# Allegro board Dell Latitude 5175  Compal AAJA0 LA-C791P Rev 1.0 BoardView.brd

Outline 223.08 x 166.9 mm; copper layers: TOP, VCC, GND1, IN1, IN2, GND2, IN3, GND3, IN4, BOTTOM. Coordinates in mm from the lower left corner of the outline.

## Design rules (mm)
constraint set DEFAULT: min track width 0.119
net group 80H-DPAUX_5.6/3.1/3.1/5.6: nets PD_AUX_N PD_AUX_P
net group DDRA-CTRL: nets M_A_CS0_N M_A_CS1_N
net group DDRB-CTRL: nets M_B_CS0_N M_B_CS1_N
net group DIFFPAIR20: nets USB20_N9_CONN USB20_P9_CONN
net group I2C0_SCL: nets I2C0_SCL I2C0_SDA
net group PCIE-WWAN: nets PCIE_PRX_DTX_N6 PCIE_PRX_DTX_P6
net group S-12/12: nets PCIE_RCOMPN PCIE_RCOMPP
net group CLK: nets CK_XDP CK_XDP# CLK_PCIE2 CLK_PCIE2# CLK_PCIE3 CLK_PCIE3# CLK_PCIE3#_R CLK_PCIE3_R CLK_PCIE4 CLK_PCIE4# CLK_PCIE4#_R CLK_PCIE4_R SKYCAM_CSI_CLK_D SKYCAM_CSI_CLK_D# SKYCAM_CSI_CLK_D#_L SKYCAM_CSI_CLK_D_L SKYCAM_USER_CSI_CLK_D SKYCAM_USER_CSI_CLK_D# SKYCAM_USER_CSI_CLK_D#_L SKYCAM_USER_CSI_CLK_D_L
net group CSI: nets SKYCAM_CSI0_D SKYCAM_CSI0_D# SKYCAM_CSI0_D#_L SKYCAM_CSI0_D_L SKYCAM_CSI1_D SKYCAM_CSI1_D# SKYCAM_CSI1_D#_L SKYCAM_CSI1_D_L SKYCAM_CSI2_D SKYCAM_CSI2_D# SKYCAM_CSI2_D#_L SKYCAM_CSI2_D_L SKYCAM_CSI3_D SKYCAM_CSI3_D# SKYCAM_CSI3_D#_L SKYCAM_CSI3_D_L SKYCAM_USER_CSI0_D SKYCAM_USER_CSI0_D# SKYCAM_USER_CSI0_D#_L SKYCAM_USER_CSI0_D_L SKYCAM_USER_CSI1_D SKYCAM_USER_CSI1_D# SKYCAM_USER_CSI1_D#_L SKYCAM_USER_CSI1_D_L
net group DDI1: nets MUX_DP_AUXN MUX_DP_AUXP MUX_DP_N0 MUX_DP_N0_C MUX_DP_N1 MUX_DP_N1_C MUX_DP_N2 MUX_DP_N2_C MUX_DP_N3 MUX_DP_N3_C MUX_DP_P0 MUX_DP_P0_C MUX_DP_P1 MUX_DP_P1_C MUX_DP_P2 MUX_DP_P2_C MUX_DP_P3 MUX_DP_P3_C PCH_DDI1_AUXN PCH_DDI1_AUXP PCH_DDI1_N0 PCH_DDI1_N0_C PCH_DDI1_N1 PCH_DDI1_N1_C PCH_DDI1_N2 PCH_DDI1_N2_C PCH_DDI1_N3 PCH_DDI1_N3_C PCH_DDI1_P0 PCH_DDI1_P0_C PCH_DDI1_P1 PCH_DDI1_P1_C PCH_DDI1_P2 PCH_DDI1_P2_C PCH_DDI1_P3 PCH_DDI1_P3_C
net group DDI1-DF12/15: nets PD_SBU1 PD_SBU2 USBC_SBU1 USBC_SBU1_R USBC_SBU2 USBC_SBU2_R
net group DDI2: nets BASE_DP_AUXN BASE_DP_AUXP BASE_DP_CLK_AUXP BASE_DP_CLK_AUXP_R BASE_DP_DAT_AUXN BASE_DP_DAT_AUXN_R BASE_DP_N0 BASE_DP_N0_C BASE_DP_N1 BASE_DP_N1_C BASE_DP_N2 BASE_DP_N2_C BASE_DP_N3 BASE_DP_N3_C BASE_DP_P0 BASE_DP_P0_C BASE_DP_P1 BASE_DP_P1_C BASE_DP_P2 BASE_DP_P2_C BASE_DP_P3 BASE_DP_P3_C HDMI_LANE_N0 HDMI_LANE_N0_C HDMI_LANE_N1 HDMI_LANE_N1_C HDMI_LANE_N2 HDMI_LANE_N2_C HDMI_LANE_N3 HDMI_LANE_N3_C HDMI_LANE_P0 HDMI_LANE_P0_C HDMI_LANE_P1 HDMI_LANE_P1_C HDMI_LANE_P2 HDMI_LANE_P2_C HDMI_LANE_P3 HDMI_LANE_P3_C PCH_DDI2_AUXN PCH_DDI2_AUXN_C PCH_DDI2_AUXP PCH_DDI2_AUXP_C PCH_DDI2_N0 PCH_DDI2_N0_C PCH_DDI2_N1 PCH_DDI2_N1_C PCH_DDI2_N2 PCH_DDI2_N2_C PCH_DDI2_N3 PCH_DDI2_N3_C PCH_DDI2_P0 PCH_DDI2_P0_C PCH_DDI2_P1 PCH_DDI2_P1_C PCH_DDI2_P2 PCH_DDI2_P2_C PCH_DDI2_P3 PCH_DDI2_P3_C RP_DP_CLK_AUXP RP_DP_DAT_AUXN RP_DP_N0 RP_DP_N0_C RP_DP_N1 RP_DP_N1_C RP_DP_N2 RP_DP_N2_C RP_DP_N3 RP_DP_N3_C RP_DP_P0 RP_DP_P0_C RP_DP_P1 RP_DP_P1_C RP_DP_P2 RP_DP_P2_C RP_DP_P3 RP_DP_P3_C TMDS_L_TX0N TMDS_L_TX0P TMDS_L_TX1N TMDS_L_TX1P TMDS_L_TX2N TMDS_L_TX2P TMDS_L_TXCN TMDS_L_TXCP TMDS_TX0N TMDS_TX0P TMDS_TX1N TMDS_TX1P TMDS_TX2N TMDS_TX2P TMDS_TXCN TMDS_TXCP
net group DDRA-CKE: nets M_A_CKE0 M_A_CKE1 M_A_CKE2 M_A_CKE3 M_A_ODT0
net group DDRA-CLK: nets M_A_CK_DDR0_DN M_A_CK_DDR0_DP M_A_CK_DDR1_DN M_A_CK_DDR1_DP
net group DDRA-D0: nets M_A_DQ_0 M_A_DQ_1 M_A_DQ_2 M_A_DQ_3 M_A_DQ_4 M_A_DQ_5 M_A_DQ_6 M_A_DQ_7 M_A_DQS_DN_0 M_A_DQS_DP_0
net group DDRA-D1: nets M_A_DQ_8 M_A_DQ_9 M_A_DQ_10 M_A_DQ_11 M_A_DQ_12 M_A_DQ_13 M_A_DQ_14 M_A_DQ_15 M_A_DQS_DN_1 M_A_DQS_DP_1
net group DDRA-D2: nets M_A_DQ_16 M_A_DQ_17 M_A_DQ_18 M_A_DQ_19 M_A_DQ_20 M_A_DQ_21 M_A_DQ_22 M_A_DQ_23 M_A_DQS_DN_2 M_A_DQS_DP_2
net group DDRA-D3: nets M_A_DQ_24 M_A_DQ_25 M_A_DQ_26 M_A_DQ_27 M_A_DQ_28 M_A_DQ_29 M_A_DQ_30 M_A_DQ_31 M_A_DQS_DN_3 M_A_DQS_DP_3
net group DDRA-D4: nets M_A_DQ_32 M_A_DQ_33 M_A_DQ_34 M_A_DQ_35 M_A_DQ_36 M_A_DQ_37 M_A_DQ_38 M_A_DQ_39 M_A_DQS_DN_4 M_A_DQS_DP_4
net group DDRA-D5: nets M_A_DQ_40 M_A_DQ_41 M_A_DQ_42 M_A_DQ_43 M_A_DQ_44 M_A_DQ_45 M_A_DQ_46 M_A_DQ_47 M_A_DQS_DN_5 M_A_DQS_DP_5
net group DDRA-D6: nets M_A_DQ_48 M_A_DQ_49 M_A_DQ_50 M_A_DQ_51 M_A_DQ_52 M_A_DQ_53 M_A_DQ_54 M_A_DQ_55 M_A_DQS_DN_6 M_A_DQS_DP_6
net group DDRA-D7: nets M_A_DQ_56 M_A_DQ_57 M_A_DQ_58 M_A_DQ_59 M_A_DQ_60 M_A_DQ_61 M_A_DQ_62 M_A_DQ_63 M_A_DQS_DN_7 M_A_DQS_DP_7
net group DDRA-MA: nets M_A_CA_0_0 M_A_CA_0_1 M_A_CA_0_2 M_A_CA_0_3 M_A_CA_0_4 M_A_CA_0_5 M_A_CA_0_6 M_A_CA_0_7 M_A_CA_0_8 M_A_CA_0_9 M_A_CA_1_0 M_A_CA_1_1 M_A_CA_1_2 M_A_CA_1_3 M_A_CA_1_4 M_A_CA_1_5 M_A_CA_1_6 M_A_CA_1_7 M_A_CA_1_8 M_A_CA_1_9
net group DDRB-CKE: nets M_B_CKE0 M_B_CKE1 M_B_CKE2 M_B_CKE3 M_B_ODT0
net group DDRB-CLK: nets M_B_CK_DDR0_DN M_B_CK_DDR0_DP M_B_CK_DDR1_DN M_B_CK_DDR1_DP
net group DDRB-D0: nets M_B_DQ_0 M_B_DQ_1 M_B_DQ_2 M_B_DQ_3 M_B_DQ_4 M_B_DQ_5 M_B_DQ_6 M_B_DQ_7 M_B_DQS_DN_0 M_B_DQS_DP_0
net group DDRB-D1: nets M_B_DQ_8 M_B_DQ_9 M_B_DQ_10 M_B_DQ_11 M_B_DQ_12 M_B_DQ_13 M_B_DQ_14 M_B_DQ_15 M_B_DQS_DN_1 M_B_DQS_DP_1
net group DDRB-D2: nets M_B_DQ_16 M_B_DQ_17 M_B_DQ_18 M_B_DQ_19 M_B_DQ_20 M_B_DQ_21 M_B_DQ_22 M_B_DQ_23 M_B_DQS_DN_2 M_B_DQS_DP_2
net group DDRB-D3: nets M_B_DQ_24 M_B_DQ_25 M_B_DQ_26 M_B_DQ_27 M_B_DQ_28 M_B_DQ_29 M_B_DQ_30 M_B_DQ_31 M_B_DQS_DN_3 M_B_DQS_DP_3
net group DDRB-D4: nets M_B_DQ_32 M_B_DQ_33 M_B_DQ_34 M_B_DQ_35 M_B_DQ_36 M_B_DQ_37 M_B_DQ_38 M_B_DQ_39 M_B_DQS_DN_4 M_B_DQS_DP_4
net group DDRB-D5: nets M_B_DQ_40 M_B_DQ_41 M_B_DQ_42 M_B_DQ_43 M_B_DQ_44 M_B_DQ_45 M_B_DQ_46 M_B_DQ_47 M_B_DQS_DN_5 M_B_DQS_DP_5
net group DDRB-D6: nets M_B_DQ_48 M_B_DQ_49 M_B_DQ_50 M_B_DQ_51 M_B_DQ_52 M_B_DQ_53 M_B_DQ_54 M_B_DQ_55 M_B_DQS_DN_6 M_B_DQS_DP_6
net group DDRB-D7: nets M_B_DQ_56 M_B_DQ_57 M_B_DQ_58 M_B_DQ_59 M_B_DQ_60 M_B_DQ_61 M_B_DQ_62 M_B_DQ_63 M_B_DQS_DN_7 M_B_DQS_DP_7
net group DDRB-MA: nets M_B_CA_0_0 M_B_CA_0_1 M_B_CA_0_2 M_B_CA_0_3 M_B_CA_0_4 M_B_CA_0_5 M_B_CA_0_6 M_B_CA_0_7 M_B_CA_0_8 M_B_CA_0_9 M_B_CA_1_0 M_B_CA_1_1 M_B_CA_1_2 M_B_CA_1_3 M_B_CA_1_4 M_B_CA_1_5 M_B_CA_1_6 M_B_CA_1_7 M_B_CA_1_8 M_B_CA_1_9
net group DEFAULT: nets CL_RST#
net group DMIC: nets DMIC_CLK1 DMIC_CLK1_R DMIC_CLK2 DMIC_CLK2_R DMIC_DATA1 DMIC_DATA1_R DMIC_DATA2 DMIC_DATA2_R
net group EC: nets JTAG_CLK JTAG_TDI JTAG_TDO JTAG_TMS
net group EDP: nets EDP_AUXN EDP_AUXN_CONN EDP_AUXN_R EDP_AUXP EDP_AUXP_CONN EDP_AUXP_R EDP_TXN_P0 EDP_TXN_P0_CONN EDP_TXN_P0_R EDP_TXN_P1 EDP_TXN_P1_CONN EDP_TXN_P1_R EDP_TXP_P0 EDP_TXP_P0_CONN EDP_TXP_P0_R EDP_TXP_P1 EDP_TXP_P1_CONN EDP_TXP_P1_R
net group HDA: nets HDA_BIT_CLK HDA_BIT_CLK_L HDA_RST# HDA_RST#_L HDA_SDI0 HDA_SDIN0_AUDIO HDA_SDOUT HDA_SDOUT_L HDA_SYNC HDA_SYNC_L
net group I2C: nets BASE_SMBCLK BASE_SMBDAT CHG_SMBCLK CHG_SMBCLK_R CHG_SMBDAT CHG_SMBDAT_R CL_CLK CL_DATA CLK_SMB DAT_SMB GNSS_SCL GNSS_SCL_L GNSS_SDA GNSS_SDA_L I2C0_SCL_AMP I2C0_SCL_AMP_R I2C0_SCL_AUD I2C0_SDA_AMP I2C0_SDA_AMP_R I2C0_SDA_AUD ISH_I2C0_SCL ISH_I2C0_SDA ISH_I2C1_SCL ISH_I2C1_SDA PBAT_SMBCLK PBAT_SMBDAT PD_DEBUG1 PD_DEBUG2 SKYCAM_I2C_CLK SKYCAM_I2C_DATA SMBCLK SMBDATA SML0CLK SML0DATA SML1_SMBCLK SML1_SMBDAT TS_I2C_SCL TS_I2C_SDA UF_I2C_CLK UF_I2C_DATA USH_PS_SMBDAT
net group LPC: nets CLK_LPC_DEBUG CLK_PCI_MEC CLKOUT_LPC0 CLKOUT_LPC1 LPC_AD0 LPC_AD1 LPC_AD2 LPC_AD3 LPC_FRAME#
net group OTHER: nets PBTN_OUT#_R SYS_PWROK TS_INT# TS_INT#_R XDP_PRSENT
net group PCH_JTAG: nets PCH_JTAG_TCK PCH_JTAG_TDI PCH_JTAG_TDO PCH_JTAG_TMS PCH_JTAG_TRST# PCH_JTAGX XDP_TCK1
net group PCIE-C: nets PCIE_PRX_DTX_N6_C PCIE_PRX_DTX_N6_RP PCIE_PRX_DTX_P6_C PCIE_PRX_DTX_P6_RP PCIE_PTX_DRX_N6 PCIE_PTX_DRX_N6_C PCIE_PTX_DRX_N6_RP PCIE_PTX_DRX_N6_RP_C PCIE_PTX_DRX_P6 PCIE_PTX_DRX_P6_C PCIE_PTX_DRX_P6_RP PCIE_PTX_DRX_P6_RP_C
net group PCIE-S: nets PCIE_PRX_DTX_N7 PCIE_PRX_DTX_N7_R PCIE_PRX_DTX_N8 PCIE_PRX_DTX_P7 PCIE_PRX_DTX_P7_R PCIE_PRX_DTX_P8 PCIE_PTX_DRX_N7 PCIE_PTX_DRX_N7_C PCIE_PTX_DRX_N8 PCIE_PTX_DRX_N8_C PCIE_PTX_DRX_P7 PCIE_PTX_DRX_P7_C PCIE_PTX_DRX_P8 PCIE_PTX_DRX_P8_C
net group PCIE-WLAN: nets PCIE_PRX_DTX_N9 PCIE_PRX_DTX_P9 PCIE_PTX_DRX_N9 PCIE_PTX_DRX_N9_C PCIE_PTX_DRX_P9 PCIE_PTX_DRX_P9_C
net group POWERS: nets +0.85VS_VCCIOP +0.95V_PRIMP +1.0V_APLL +1.0V_MPHYGT +1.0V_MPHYPLL +1.0V_PRIMP +1.0V_VCCPLL +1.0V_VCCST +1.0V_XDP +1.0VS_VCCSTG +1.2V_VCCPLL_OC +1.2V_WF_DVDD +1.8V_IO_OUT +1.8V_MEM +1.8V_PCH_GPP +1.8V_PRIMP +1.8V_UF_VDD +1.8V_WF_DOVDD +1.8VA_LDO_PD +1.8VD_LDO_PD +1.8VS +1.8VS_AUDIO +2.8V_UF_AVDD +2.8V_VCM_OUT +3.3V_PCH_GPP +3.3V_VCCSPI +3.3V_VOUT_PD +3.3VDX_SSD +3V_1.8V_HDA +3V_LDO +3V_PRIMP +3VALW_EC +3VALW_EC_L +3VALW_PD +3VALWP +3VLP +3VS_AUDIO +3VS_CAM +3VS_HP +3VS_TPM +3VS_TS +3VS_WLAN +3VS_WWAN +5V_DOCK +5VALWP +AC_DOCK_IN +AMP_AVDD1 +AVDD1 +BAT_TABLET +BATT +DVDDIO +INV_PWR_SRC +LED_AN +PVDD +RTCVCC_EC +VCCAPLLEBB_1P0 +VCCCLK1 +VCCCLK2 +VCCCLK3 +VCCCLK4 +VCCCLK5 +VCCCLK6 +VCCPRIM_1P0 +VCCPRIM_3P3 +VCCPRIM_CORE +VCCSRAM_1P0 +VDDQ_CPU_CLK +VDISPLAY_VCC AMP_LDO_A1.5V N20422143 N21803574 N21803688 N55958618 N55958653 PLL_VDD
net group S-8/8: nets H_CATERR H_PROCHOT# H_PROCHOT#_R H_VCCST_PWRGD
net group S-10/10: nets HP2_D_L HP2_D_L_C HP2_D_L_R HP2_D_R HP2_D_R_C HP2_D_R_R HP_IN_L_N HP_IN_L_P HP_IN_R_N HP_IN_R_P LINE1_L LINE1_R LINE_L LINE_R MIC1-VREFO_L MIC1-VREFO_R RING2 SPK_L+ SPK_L+_L SPK_L- SPK_L-_L SPK_R-_L UIM_DET UIM_DET# UIM_RESET USH_PS_SMBCLK
net group S-15/15: nets CSI2_COMP EMMC_RCOMP NFC_RST# OSC_IN OSC_OUT PCH_PLTRST# PCH_RTCX1 PCH_RTCX2 PCH_SRTCRST# RTC_RST# SDIO_RCOMP SSD_RST# SYS_RESET# TS_RST# UF_SENSOR_RST# UF_SENSOR_RST#_R UIM_CLK UIM_DATA USB2_COMP USH_RST#_R VCCGT_SENSE VCCSA_SENSE VCCSENSE VSSGT_SENSE VSSSA_SENSE VSSSENSE WF_SENSOR_RST# WF_SENSOR_RST#_R WLAN_RST#_Q WWAN_RST# WWAN_RST#_Q XTAL24_IN XTAL24_OUT
net group S-18/18: nets ALERT# H_PECI H_THERMTRIP# PECI_EC SDA
net group S-20/20: nets +V_DDR_0_DQ_VREF +V_DDR_1_DQ_VREF +V_DDR_VREF_CA CFG_RCOMP CPU_POPIRCOMP MEC_XTAL1 MEC_XTAL2 PCH_OPIRCOMP
net group S-20/25: nets DDR_RCOMP_0 DDR_RCOMP_1 DDR_RCOMP_2
net group S-25/25: nets +EDP_COM
net group SPI-ITOUCH: nets PCH_SPI1_CLK PCH_SPI1_CS# PCH_SPI1_IO2 PCH_SPI1_IO3 PCH_SPI1_MISO PCH_SPI1_MOSI
net group SPI-ROM: nets PCH_SPI_CLK PCH_SPI_CLK_R PCH_SPI_CS0# PCH_SPI_CS1# PCH_SPI_CS2# PCH_SPI_CS2#_R PCH_SPI_IO2 PCH_SPI_IO3 PCH_SPI_SCLK PCH_SPI_SI PCH_SPI_SI_MOSI PCH_SPI_SO PCH_SPI_SO_R SPI_CLK_ROM1 SPI_CLK_ROM2 SPI_IO2_ROM1 SPI_IO2_ROM2 SPI_IO3_ROM1 SPI_IO3_ROM2 SPI_PCH_CLK SPI_PCH_CS0# SPI_PCH_CS1# SPI_PCH_IO2 SPI_PCH_IO3 SPI_PCH_SI SPI_PCH_SO SPI_SI_ROM1 SPI_SI_ROM2 SPI_SO_ROM1 SPI_SO_ROM2
net group SVID: nets SOC_SVID_ALERT# SOC_SVID_CLK SOC_SVID_DAT SVID_ALERT# SVID_CLK SVID_DAT
net group USB2.0: nets USB20_N1 USB20_N1_R USB20_N2 USB20_N2_R USB20_N3 USB20_N3_CONN USB20_N5 USB20_N7 USB20_N9 USB20_N9_SW USB20_P1 USB20_P1_R USB20_P2 USB20_P2_R USB20_P3 USB20_P3_CONN USB20_P5 USB20_P7 USB20_P9 USB20_P9_SW USBC_BOT_N USBC_BOT_N_R USBC_BOT_P USBC_BOT_P_R USBC_TOP_N USBC_TOP_N_R USBC_TOP_P USBC_TOP_P_R
net group USB3.0: nets USB3RN1 USB3RN1_C USB3RN1_RP USB3RN1_RP_C USB3RN2 USB3RN2_CON USB3RN3 USB3RN4 USB3RN4_CON USB3RN5 USB3RN5_CON USB3RP1 USB3RP1_C USB3RP1_RP USB3RP1_RP_C USB3RP2 USB3RP2_CON USB3RP3 USB3RP4 USB3RP4_CON USB3RP5 USB3RP5_CON USB3TN1 USB3TN1_C USB3TN1_RP USB3TN1_RP_C USB3TN2 USB3TN2_CON USB3TN2_R USB3TN3 USB3TN4 USB3TN4_CON USB3TN5 USB3TN5_C USB3TN5_CON USB3TP1 USB3TP1_C USB3TP1_RP USB3TP1_RP_C USB3TP2 USB3TP2_CON USB3TP2_R USB3TP3 USB3TP4 USB3TP4_CON USB3TP5 USB3TP5_C USB3TP5_CON USBC_RX1N USBC_RX1P USBC_RX2N USBC_RX2P USBC_TX1N USBC_TX1P USBC_TX2N USBC_TX2P
net group W-20: nets DDR_0_DQ_VREF DDR_1_DQ_VREF DDR_VREF_CA
net group XDP: nets CFG0 CFG1 CFG2 CFG3 CFG4 CFG5 CFG6 CFG7 CFG8 CFG9 CFG10 CFG11 CFG12 CFG13 CFG14 CFG15 CFG16 CFG17 CFG18 CFG19 CPU_XDP_TCK CPU_XDP_TDI CPU_XDP_TDO CPU_XDP_TMS CPU_XDP_TRST# ITP_PMODE PCH_RSMRST# PCH_RSMRST#_R PLT_RST# PM_SYS_RESET# PWRGD_XDP SIO_PWRBTN# XDP_BPM#0 XDP_BPM#1 XDP_DBRESET# XDP_OBS0 XDP_OBS1 XDP_PIN1 XDP_PRSENT# XDP_PWRBTN# XDP_RST# XDP_TCK0 XDP_TDI XDP_TDO XDP_TMS XDP_TRST#
nets with their own width: min track width 0.254; nets SPK_R-_R

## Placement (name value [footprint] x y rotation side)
C1  47P_0402_50V8J  [C_0402]  212.83 143.91 0 top
C2  0.1U_0201_10V6K  [C_0201]  210.27 143.89 180 top
C3  33P_0201_50V8J  [C_0201]  210.27 143.26 180 top
C4  22U_0603_6.3V6M  [C_0603]  212.59 142.76 0 top
C5  10U_0402_6.3V6M  [C_0402]  57.19 142.36 180 top
C6  0.1U_0201_10V6K  [C_0201]  52.76 142.23 180 top
C7  0.1U_0201_10V6K  [C_0201]  198.02 141.86 90 top
C8  0.1U_0201_10V6K  [C_0201]  209.97 141.58 270 top
C9  0.1U_0201_10V6K  [C_0201]  49.17 140.67 270 top
C10  15P_0402_50V8J  [C_0402]  44.98 140.12 180 top
C11  15P_0402_50V8J  [C_0402]  45.8 140.12 0 top
C12  2200P_0402_25V7K  [C_0402]  47.57 139.59 90 top
C13  100U_A1_6.3VM_R70M  [C_NEC]  212.57 139.79 0 top
C14  0.1U_0201_10V6K  [C_0201]  205.78 139.69 180 top
C15  0.1U_0201_10V6K  [C_0201]  57.2 139.92 270 top
C16  0.1U_0201_10V6K  [C_0201]  45.9 139.41 0 top
C17  0.1U_0201_10V6K  [C_0201]  44.53 139.39 180 top
C18  0.1U_0201_10V6K  [C_0201]  205.78 139.13 180 top
C19  100P_0402_50V8J  [C_0402]  216.18 139.39 270 top
C20  0.1U_0201_10V6K  [C_0201]  43.92 138.22 90 top
C21  0.1U_0201_10V6K  [C_0201]  57.23 138 90 top
C22  0.1U_0201_10V6K  [C_0201]  192.24 137.73 0 top
C23  0.22U_0402_10V6K  [C_0402]  197.88 137.58 0 top
C24  0.1U_0201_10V6K  [C_0201]  195.01 137.25 0 top
C25  0.1U_0201_10V6K  [C_0201]  49.81 137.53 270 top
C26  0.1U_0201_10V6K  [C_0201]  189.65 137.15 180 top
C27  0.1U_0201_10V6K  [C_0201]  57.2 136.77 90 top
C28  1U_0402_6.3V6K  [C_0402]  46.58 136.31 90 top
C29  22U_0603_6.3V6M  [C_0603]  44.32 137.15 270 top
C30  22U_0603_6.3V6M  [C_0603]  45.52 137.15 270 top
C31  0.1U_0201_10V6K  [C_0201]  6.71 136.35 270 top
C32  0.1U_0201_10V6K  [C_0201]  193.79 135.24 180 top
C33  0.1U_0201_10V6K  [C_0201]  189.29 135.22 0 top
C34  0.1U_0201_10V6K  [C_0201]  193.87 134.25 180 top
C35  0.1U_0201_10V6K  [C_0201]  189.32 133.32 90 top
C36  0.1U_0201_10V6K  [C_0201]  193.23 133.29 0 top
C37  0.1U_0201_10V6K  [C_0201]  193.23 132.7 0 top
C38  0.1U_0201_10V6K  [C_0201]  145.63 132.26 0 top
C39  4.7U_0402_6.3V6M  [C_0402]  124.49 132.2 180 top
C40  2.2U_0402_6.3V6M  [C_0402]  143.87 132.2 0 top
C41  68P_0201_25V8  [C_0201]  116.48 131.73 90 top
C42  1U_0201_6.3V6M  [C_0201]  131.25 132.02 180 top
C43  47P_0201_25V8J  [C_0201]  150.84 131.88 270 top
C44  0.1U_0201_10V6K  [C_0201]  137.72 131.57 90 top
C45  0.1U_0201_10V6K  [C_0201]  136.28 130.39 180 top
C46  4.7U_0402_6.3V6M  [C_0402]  128.37 131.28 90 top
C47  0.1U_0201_10V6K  [C_0201]  49.81 131.99 270 top
C48  0.1U_0201_10V6K  [C_0201]  129.11 131.27 90 top
C49  47P_0201_25V8J  [C_0201]  116.48 131.12 270 top
C50  10U_0603_6.3V6M  [C_0603]  56.74 132.23 270 top
C51  0.1U_0201_10V6K  [C_0201]  114.85 130.91 270 top
C52  0.1U_0201_10V6K  [C_0201]  114.85 131.55 90 top
C53  0.1U_0201_10V6K  [C_0201]  49.25 131.69 270 top
C54  0.1U_0201_10V6K  [C_0201]  121.98 131.36 180 top
C55  1U_0402_6.3V6K  [C_0402]  146.33 131.13 0 top
C56  0.1U_0201_10V6K  [C_0201]  119.75 131.41 270 top
C57  2.2U_0402_6.3V6M  [C_0402]  118.95 130.5 90 top
C58  0.1U_0201_10V6K  [C_0201]  118.24 130.53 90 top
C59  0.1U_0402_10V7K  [C_0402]  210.49 130.8 180 top
C60  0.1U_0201_10V6K  [C_0201]  121.97 130.76 180 top
C61  100P_0402_50V8J  [C_0402]  142.13 130.72 0 top
C62  0.1U_0201_10V6K  [C_0201]  137.92 130.58 270 top
C63  2.2U_0402_6.3V6M  [C_0402]  138.73 130.58 270 top
C64  0.1U_0201_10V6K  [C_0201]  107.07 129.99 180 top
C65  0.1U_0201_10V6K  [C_0201]  108.85 129.99 0 top
C66  0.1U_0201_10V6K  [C_0201]  213.4 129.86 0 top
C67  10U_0402_6.3V6M  [C_0402]  94.56 129.71 0 top
C68  0.1U_0201_10V6K  [C_0201]  104.99 129.9 270 top
C69  0.1U_0201_10V6K  [C_0201]  104.42 129.88 270 top
C70  68P_0201_25V8  [C_0201]  124.03 129.48 0 top
C71  .047U_0402_16V7K  [C_0402]  88.39 129.89 270 top
C72  10U_0402_6.3V6M  [C_0402]  105.73 129.85 270 top
C73  33P_0201_50V8J  [C_0201]  213.4 129.28 0 top
C74  0.01U_0402_16V7K  [C_0402]  46.84 129.07 0 top
C75  1U_0201_6.3V6M  [C_0201]  126.59 128.56 90 top
C76  0.022U_0402_16V7K~D  [C_0402]  87.48 128.64 180 top
C77  0.1U_0201_10V6K  [C_0201]  150.04 128.54 0 top
C78  47P_0402_50V8J  [C_0402]  213.16 128.54 0 top
C80  0.1U_0201_10V6K  [C_0201]  90.79 128.16 0 top
C81  0.1U_0201_10V6K  [C_0201]  131.67 127.79 90 top
C82  18P_0402_50V8J  [C_0402]  136.12 127.9 180 top
C83  18P_0402_50V8J  [C_0402]  136.98 127.88 0 top
C84  0.1U_0201_10V6K  [C_0201]  90.79 127.6 0 top
C85  22U_0603_6.3V6M  [C_0603]  212.89 127.5 0 top
C86  0.022U_0402_16V7K~D  [C_0402]  83.08 127.42 0 top
C87  0.1U_0201_10V6K  [C_0201]  204.69 126.96 180 top
C88  1U_0201_6.3V6M  [C_0201]  124.31 127.08 270 top
C89  10U_0402_6.3V6M  [C_0402]  28.55 126.6 180 top
C90  0.1U_0201_10V6K  [C_0201]  109.88 126.29 90 top
C91  0.1U_0201_10V6K  [C_0201]  101.31 126.16 90 top
C92  0.1U_0201_10V6K  [C_0201]  99.43 126.15 90 top
C93  0.1U_0201_10V6K  [C_0201]  100 126.15 90 top
C94  0.01UF_0402_25V7K  [C_0402]  134.29 126.89 270 top
C97  2200P_0402_25V7K  [C_0402]  209.32 126.25 0 top
C98  2200P_0402_25V7K  [C_0402]  149.99 125.78 90 top
C99  0.1U_0201_10V6K  [C_0201]  210.95 126.39 270 top
C100  2200P_0402_50V7K  [C_0402]  132.51 126.02 0 top
C101  0.1U_0201_10V6K  [C_0201]  104.18 125.85 0 top
C102  100U_A1_6.3VM_R70M  [C_NEC]  212.85 125.85 0 top
C103  0.1U_0201_10V6K  [C_0201]  151.32 125.76 180 top
C104  2200P_0402_25V7K  [C_0402]  106.5 125.54 180 top
C105  0.1U_0201_10V6K  [C_0201]  128.23 125.44 180 top
C106  2200P_0402_25V7K  [C_0402]  209.32 125.36 0 top
C107  10U_0402_6.3V6M  [C_0402]  93.15 124.82 90 top
C108  10U_0402_6.3V6M  [C_0402]  92.18 124.81 90 top
C109  4700P_0402_16V7K  [C_0402]  107.37 125.57 270 top
C110  2200P_0402_50V7K  [C_0402]  133.43 125.11 180 top
C111  10U_0402_6.3V6M  [C_0402]  217.27 124.4 90 top
C112  1U_0402_6.3V6K  [C_0402]  131.44 124.78 180 top
C113  0.01UF_0402_25V7K  [C_0402]  134.31 125.14 270 top
C114  1U_0402_6.3V6K  [C_0402]  146.21 124.54 180 top
C115  0.1U_0201_10V6K  [C_0201]  204.66 122.98 180 top
C116  4.7U_0402_6.3V6M  [C_0402]  128.07 124.7 270 top
C117  1U_0201_6.3V6M  [C_0201]  126.95 123.8 180 top
C118  0.1U_0201_10V6K  [C_0201]  55.5 123.69 0 top
C119  1U_0201_6.3V6M  [C_0201]  130.07 123.36 90 top
C120  10U_0402_6.3V6M  [C_0402]  86.13 123.99 270 top
C121  1U_0201_6.3V6M  [C_0201]  125.53 123.79 270 top
C122  .047U_0402_16V7K  [C_0402]  90.14 123.43 180 top
C123  0.1U_0201_10V6K  [C_0201]  7.52 122.16 180 top
C124  0.022U_0402_16V7K~D  [C_0402]  87.88 122.16 0 top
C125  10U_0603_6.3V6M  [C_0603]  130.14 121.83 180 top
C126  100P_0402_50V8J  [C_0402]  83.56 120.05 90 top
C127  0.01U_0201_10V7K  [C_0201]  214.99 118.9 90 top
C128  100P_0402_50V8J  [C_0402]  141.59 118.07 180 top
C129  0.1U_0201_10V6K  [C_0201]  215.05 116.47 0 top
C130  0.1U_0201_10V6K  [C_0201]  215.05 115.92 0 top
C131  0.1U_0201_10V6K  [C_0201]  79.76 116.18 270 top
C132  0.1U_0201_10V6K  [C_0201]  206.4 114.98 0 top
C133  0.1U_0201_10V6K  [C_0201]  25.06 114.82 0 top
C134  0.1U_0201_10V6K  [C_0201]  206.4 114.39 0 top
C135  0.1U_0201_10V6K  [C_0201]  28.17 113.69 90 top
C136  220P_0402_25V8J  [C_0402]  23.19 111.39 180 top
C137  1000P_0402_25V8J  [C_0402]  24.94 111.39 180 top
C138  0.1U_0201_10V6K  [C_0201]  29.41 110.58 0 top
C139  0.1U_0201_10V6K  [C_0201]  213.73 110.78 270 top
C140  0.1U_0201_10V6K  [C_0201]  22.91 110 90 top
C141  0.1U_0201_10V6K  [C_0201]  34.72 108.47 0 top
C142  0.1U_0201_10V6K  [C_0201]  36.84 108.47 180 top
C143  0.1U_0201_10V6K  [C_0201]  151.55 107.48 0 top
C144  1U_0201_6.3V6K  [C_0201]  139.22 106.81 90 top
C145  2200P_0402_25V7K  [C_0402]  35.38 106.59 90 top
C146  4700P_0402_16V7K  [C_0402]  36.25 106.59 90 top
C147  0.1U_0201_10V6K  [C_0201]  214.91 106.3 90 top
C148  0.1U_0201_10V6K  [C_0201]  217.2 106.3 90 top
C149  0.1U_0201_10V6K  [C_0201]  106.4 104.73 270 top
C150  0.1U_0201_10V6K  [C_0201]  106.96 104.73 270 top
C151  0.1U_0201_10V6K  [C_0201]  107.8 104.73 270 top
C152  0.1U_0201_10V6K  [C_0201]  108.36 104.73 270 top
C153  0.1U_0201_10V6K  [C_0201]  109.22 104.73 270 top
C154  0.1U_0201_10V6K  [C_0201]  109.78 104.73 270 top
C155  0.1U_0201_10V6K  [C_0201]  51.32 104.41 0 top
C156  1U_0201_6.3V6K  [C_0201]  138.4 103.86 90 top
C157  0.1U_0201_10V6K  [C_0201]  37.52 103.69 90 top
C158  2.2U_0402_6.3V6M  [C_0402]  137.67 103.39 90 top
C159  2200P_0402_25V7K  [C_0402]  46.38 103.8 180 top
C160  10U_0603_25V6M  [C_0603]  114.96 103.04 90 top
C161  0.1U_0402_16V4Z  [C_0402]  113.82 103.16 90 top
C162  1U_0402_6.3V6K  [C_0402]  43.26 103.54 180 top
C163  2200P_0402_25V7K  [C_0402]  46.35 102.91 180 top
C164  10U_0603_6.3V6M  [C_0603]  104.19 102.01 90 top
C165  10U_0603_6.3V6M  [C_0603]  105.38 102.01 90 top
C166  4700P_0402_16V7K  [C_0402]  150.72 102.89 270 top
C167  0.1U_0201_10V6K  [C_0201]  52.12 102.33 0 top
C168  33P_0402_50V8J  [C_0402]  203.77 101.39 90 top
C169  0.1U_0201_10V6K  [C_0201]  34.29 101.95 270 top
C170  2200P_0402_25V7K  [C_0402]  215.8 101.84 270 top
C171  2200P_0402_25V7K  [C_0402]  216.69 101.84 270 top
C172  4.7U_0603_6.3V6K  [C_0603]  41.22 100.68 90 top
C173  47P_0402_50V8J  [C_0402]  42.27 100.88 90 top
C174  33P_0402_50V8J  [C_0402]  194.72 100.75 90 top
C175  33P_0402_50V8J  [C_0402]  103.4 101.01 180 top
C176  0.1U_0201_10V6K  [C_0201]  104.19 101.25 270 top
C177  0.1U_0201_10V6K  [C_0201]  104.77 101.25 270 top
C178  2.2U_0402_10V6M  [C_0402]  140.08 100.93 180 top
C179  10U_0402_6.3V6M  [C_0402]  140.92 100.93 0 top
C180  0.1U_0201_10V6K  [C_0201]  49.4 101.16 270 top
C181  0.1U_0201_10V6K  [C_0201]  151.32 100.68 180 top
C182  33P_0402_50V8J  [C_0402]  197.89 99.86 0 top
C183  33P_0402_50V8J  [C_0402]  195.61 99.61 0 top
C184  0.1U_0201_10V6K  [C_0201]  207.81 98.69 180 top
C185  0.1U_0201_10V6K  [C_0201]  211.73 98.85 270 top
C186  33P_0402_50V8J  [C_0402]  194.72 98.94 270 top
C187  0.1U_0201_10V6K  [C_0201]  212.37 97.92 90 top
C188  0.1U_0201_10V6K  [C_0201]  207.81 97.91 180 top
C189  2200P_0402_25V7K  [C_0402]  40.36 74.53 0 top
C190  0.1U_0402_10V7K  [C_0402]  30.84 71.15 270 top
C191  0.1U_0402_10V7K  [C_0402]  42.72 71.5 90 top
C192  0.1U_0201_10V6K  [C_0201]  38.2 65.38 90 top
C193  0.1U_0201_10V6K  [C_0201]  38.76 65.38 90 top
C194  0.1U_0201_10V6K  [C_0201]  39.73 65.97 270 top
C195  0.1U_0201_10V6K  [C_0201]  40.28 65.97 270 top
C196  0.1U_0201_10V6K  [C_0201]  39.73 57.79 270 top
C197  0.1U_0201_10V6K  [C_0201]  40.28 57.79 270 top
C198  0.1U_0201_10V6K  [C_0201]  24.43 61.92 270 top
C199  10U_0603_6.3V6M  [C_0603]  30.57 63.78 0 top
C200  1U_0402_6.3V6K  [C_0402]  30.81 62.74 0 top
C201  0.1U_0402  [C_0402]  21.96 44.64 90 top
C202  10U_0402  [C_0402]  22.82 44.64 90 top
C203  0.22U_0402_16V7K  [C_0402]  34.93 48.7 90 top
C204  10U_0402_6.3V6M  [C_0402]  35.97 46.83 90 top
C205  0.01U_0402  [C_0402]  21.97 43.36 270 top
C206  10U_0402_6.3V6M  [C_0402]  37.46 44.43 90 top
C207  2.2U_0402_6.3V6M  [C_0402]  38.47 44.29 90 top
C208  0.1U_0201_10V6K  [C_0201]  36.75 44.31 90 top
C209  1U_0201_6.3V6K  [C_0201]  40.38 44.31 90 top
C212  2.2U_0402_6.3V6M  [C_0402]  33.22 43.93 90 top
C213  2.2U_0402_6.3V6M  [C_0402]  41.25 43.04 270 top
C214  1U_0201_6.3V6K  [C_0201]  32.73 42.48 180 top
C215  10U_0603_25V6M  [C_0603]  42.3 42.43 0 top
C216  10U_0603_25V6M  [C_0603]  42.3 41.19 0 top
C217  10U_0603_25V6M  [C_0603]  42.33 39.94 0 top
C218  10U_0603_25V6M  [C_0603]  42.33 38.73 0 top
C219  220P_0201_25V7K  [C_0201]  32.98 38.65 180 top
C220  10U_0603_25V6M  [C_0603]  41.25 39.31 270 top
C221  220P_0201_25V7K  [C_0201]  32.98 38.06 180 top
C222  1U_0603_25V6  [C_0603]  33.39 36.24 180 top
C223  4.7U_0402_6.3V6M  [C_0402]  40.23 35.21 270 top
C224  4.7U_0402_6.3V6M  [C_0402]  41.12 35.21 270 top
C225  10U_0402_6.3V6M  [C_0402]  63.08 143.14 180 bottom
C226  .047U_0402_16V7K  [C_0402]  64.85 143.14 180 bottom
C227  10U_0402_6.3V6M  [C_0402]  61.3 143.13 180 bottom
C228  10U_0402_6.3V6M  [C_0402]  69.89 143.12 0 bottom
C229  10U_0402_6.3V6M  [C_0402]  68 143.1 0 bottom
C230  10U_0402_6.3V6M  [C_0402]  58.48 142.69 270 bottom
C231  1U_0402_6.3V6K  [C_0402]  197.59 142.6 180 bottom
C232  10U_0402_6.3V6M  [C_0402]  58.48 140.92 270 bottom
C233  1U_0402_6.3V4Z  [C_0402]  188.85 139.51 90 bottom
C234  0.1U_0201_10V6K  [C_0201]  193.29 139.27 90 bottom
C235  27P_0402_50V8J  [C_0402]  196.34 139.31 0 bottom
C236  27P_0402_50V8J  [C_0402]  195.33 139.31 180 bottom
C237  10U_0402_6.3V6M  [C_0402]  58.5 139.14 270 bottom
C238  2200P_0402_50V7K  [C_0402]  186.31 138.34 0 bottom
C239  2200P_0402_50V7K  [C_0402]  187.25 137.35 180 bottom
C240  10U_0402_6.3V6M  [C_0402]  58.49 137.37 270 bottom
C241  0.1U_0402_10V7K  [C_0402]  187.2 136.13 180 bottom
C242  2200P_0402_50V7K  [C_0402]  187.2 135.17 180 bottom
C243  10U_0402_6.3V6M  [C_0402]  74.92 135.14 0 bottom
C244  10U_0402_6.3V6M  [C_0402]  94.18 135.13 180 bottom
C245  10U_0402_6.3V6M  [C_0402]  92.37 135.13 180 bottom
C246  10U_0402_6.3V6M  [C_0402]  89.6 135.11 0 bottom
C247  10U_0402_6.3V6M  [C_0402]  85.54 135.08 180 bottom
C248  10U_0402_6.3V6M  [C_0402]  83.73 135.07 180 bottom
C249  4700P_0402_25V7K  [C_0402]  196.42 134.84 0 bottom
C250  4.7U_0603_6.3V6K  [C_0603]  196.58 133.8 0 bottom
C251  10U_0402_6.3V6M  [C_0402]  81.77 133.16 90 bottom
C252  10U_0402_6.3V6M  [C_0402]  73.43 134 270 bottom
C253  10U_0402_6.3V6M  [C_0402]  95.66 132.26 90 bottom
C254  10U_0402_6.3V6M  [C_0402]  58.48 132.22 90 bottom
C255  0.1U_0201_10V6K  [C_0201]  196.41 132.63 0 bottom
C256  10U_0402_6.3V6M  [C_0402]  81.75 131.43 90 bottom
C257  100P_0402_50V8J  [C_0402]  78.83 131.15 180 bottom
C258  10U_0402_6.3V6M  [C_0402]  95.66 130.49 90 bottom
C259  10U_0402_6.3V6M  [C_0402]  73.53 131.4 270 bottom
C260  10U_0402_6.3V6M  [C_0402]  81.74 129.53 90 bottom
C261  4.7P_0402_50V8C  [C_0402]  190.86 129.3 90 bottom
C262  0.1U_0201_10V6K  [C_0201]  194.64 129.85 270 bottom
C263  0.1U_0201_10V6K  [C_0201]  194.06 129.85 270 bottom
C264  0.1U_0201_10V6K  [C_0201]  193.47 129.85 270 bottom
C265  0.1U_0201_10V6K  [C_0201]  195.78 129.82 270 bottom
C266  0.1U_0201_10V6K  [C_0201]  195.2 129.82 270 bottom
C267  10U_0603_6.3V6M  [C_0603]  197.38 129.52 270 bottom
C268  .047U_0402_16V7K  [C_0402]  66.18 128.8 0 bottom
C269  10U_0402_6.3V6M  [C_0402]  64.41 128.79 0 bottom
C270  10U_0402_6.3V6M  [C_0402]  61.82 128.79 180 bottom
C271  10U_0402_6.3V6M  [C_0402]  69.62 128.74 0 bottom
C276  10U_0402_6.3V6M  [C_0402]  95.66 125.95 90 bottom
C282  10U_0402_6.3V6M  [C_0402]  85.76 120.69 180 bottom
C283  10U_0402_6.3V6M  [C_0402]  93.95 120.69 180 bottom
C284  10U_0402_6.3V6M  [C_0402]  89.74 120.69 180 bottom
C285  10U_0402_6.3V6M  [C_0402]  87.05 120.69 0 bottom
C294  1U_0603_25V6K  [C_0603]  114.34 110.99 180 bottom
C295  0.1U_0402_10V7K  [C_0402]  27.59 110.59 0 bottom
C296  4.7U_0603_6.3V6K  [C_0603]  25.64 108.83 90 bottom
C297  0.1U_0402_10V7K  [C_0402]  179.62 109.71 180 bottom
C298  0.1U_0201_10V6K  [C_0201]  117.28 109.18 90 bottom
C299  0.1U_0201_10V6K  [C_0201]  24.71 108.84 90 bottom
C300  33P_0402_50V8J  [C_0402]  33.65 108.88 180 bottom
C301  2.2U_0402_25V6M  [C_0402]  113.79 106.97 270 bottom
C302  0.1U_0402_25V6  [C_0402]  117.58 105.43 0 bottom
C304  0.1U_0201_10V6K  [C_0201]  172.36 103.57 90 bottom
C305  15P_0402_50V8J  [C_0402]  173.13 103.72 90 bottom
C306  0.1U_0402_10V7K  [C_0402]  180.3 104.89 270 bottom
C307  2.2U_0402_6.3V6M  [C_0402]  58.45 102.94 90 bottom
C308  0.1U_0201_10V6K  [C_0201]  57.71 103.58 270 bottom
C309  0.1U_0201_10V6K  [C_0201]  57.15 103.58 270 bottom
C310  0.1U_0201_10V6K  [C_0201]  56.59 103.56 270 bottom
C311  0.1U_0201_10V6K  [C_0201]  56.03 103.56 270 bottom
C312  0.1U_0201_10V6K  [C_0201]  55.47 103.56 270 bottom
C313  0.1U_0201_10V6K  [C_0201]  54.91 103.56 270 bottom
C314  0.1U_0201_10V6K  [C_0201]  53.24 103.56 270 bottom
C315  0.1U_0201_10V6K  [C_0201]  52.68 103.56 270 bottom
C316  0.1U_0201_10V6K  [C_0201]  52.12 102.97 90 bottom
C317  0.1U_0201_10V6K  [C_0201]  173.28 102.83 180 bottom
C318  2200P_0402_25V7K  [C_0402]  175.54 102.47 180 bottom
C319  1U_0402_6.3V6K  [C_0402]  61.77 102.76 270 bottom
C320  0.1U_0201_10V6K  [C_0201]  173.28 102.26 180 bottom
C321  0.1U_0201_10V6K  [C_0201]  73.76 101.93 90 bottom
C322  0.1U_0201_10V6K  [C_0201]  61.04 102.43 270 bottom
C323  1U_0402_6.3V6K  [C_0402]  67.18 101.55 180 bottom
C324  0.1U_0201_10V6K  [C_0201]  68.45 101.54 270 bottom
C325  1000P_0402_50V7K  [C_0402]  65.42 100.59 90 bottom
C326  1000P_0402_50V7K  [C_0402]  64.53 100.59 90 bottom
C327  0.01U_0201_10V6K  [C_0201]  49.19 99.91 180 bottom
C328  0.1U_0201_10V6K  [C_0201]  62.28 99.89 180 bottom
C329  0.1U_0201_10V6K  [C_0201]  67.28 99.9 270 bottom
C330  0.1U_0201_10V6K  [C_0201]  62.28 99.33 180 bottom
C331  0.1U_0201_10V6K  [C_0201]  73.62 96.31 0 bottom
C332  0.1U_0201_10V6K  [C_0201]  70.14 96.15 0 bottom
C333  0.01U_0201_10V6K  [C_0201]  49.16 96 180 bottom
C334  0.1U_0201_10V6K  [C_0201]  64.92 96.17 270 bottom
C335  0.1U_0201_10V6K  [C_0201]  72.36 96.12 270 bottom
C336  0.1U_0201_10V6K  [C_0201]  68.91 96.12 270 bottom
C337  1U_0402_6.3V6K  [C_0402]  66.52 96.18 270 bottom
C338  1U_0402_6.3V6K  [C_0402]  64.19 96.18 270 bottom
C339  0.1U_0201_10V6K  [C_0201]  73.04 95.52 0 bottom
C340  0.1U_0201_10V6K  [C_0201]  61.01 95.79 270 bottom
C341  100P_0402_50V8J  [C_0402]  21.01 66.39 180 bottom
C342  2200P_0402_25V7K  [C_0402]  20.62 56.25 270 bottom
C343  47U_0805_6.3V6M  [C_0805]  16.74 42.27 90 bottom
C344  47U_0805_6.3V6M  [C_0805]  18.49 42.24 90 bottom
C345  0.1U_0201_10V6K  [C_0201]  15.57 42.6 90 bottom
C346  0.1U_0201_10V6K  [C_0201]  21.06 42.4 270 bottom
C347  0.1U_0201_10V6K  [C_0201]  20.47 42.4 270 bottom
C348  0.01U_0402_25V7K  [C_0402]  18.06 25.67 270 bottom
C349  0.01U_0402_25V7K  [C_0402]  17.09 25.67 270 bottom
C350  0.01U_0402_25V7K  [C_0402]  16.13 25.67 270 bottom
C351  0.01U_0402_25V7K  [C_0402]  18.31 22.52 90 bottom
C352  100P_0402_50V8J  [C_0402]  25.86 16.74 0 bottom
C353  47P_0201_25V8J  [C_0201]  139.48 132.32 180 top
C354  47P_0201_25V8J  [C_0201]  117.07 130.25 90 top
C355  47P_0201_25V8J  [C_0201]  136.28 130.98 180 top
C356  47P_0201_25V8J  [C_0201]  117.65 130.25 90 top
C357  47P_0201_25V8J  [C_0201]  130.66 123.34 90 top
C358  47P_0201_25V8J  [C_0201]  124.9 128.56 180 top
C359  47P_0201_25V8J  [C_0201]  118.88 132.32 180 top
C360  47P_0201_25V8J  [C_0201]  138.3 131.73 90 top
C361  47P_0201_25V8J  [C_0201]  142.48 132.35 180 top
C362  47P_0201_25V8J  [C_0201]  132.42 130.24 0 top
C363  2200P_0402_25V7K  [C_0402]  194.51 104.38 180 bottom
C364  0.1U_0402_25V6  [C_0402]  194.51 105.25 180 bottom
C365  2200P_0402_25V7K  [C_0402]  151.76 109.67 90 top
C366  0.1U_0402_25V6  [C_0402]  150.9 109.67 90 top
C367  22U_0603_6.3V6M  [C_0603]  136.94 131.89 180 top
C368  22U_0603_6.3V6M  [C_0603]  113.92 130.71 90 top
C369  0.33U_0402_10V6K  [C_0402]  208.38 111.9 180 bottom
CA1  680P_0201_50V7K  [C_0201]  9.77 144.77 0 top
CA2  680P_0201_50V7K  [C_0201]  8.46 139.13 270 top
CA3  100P_0201_25V8J  [C_0201]  6.69 142.26 0 top
CA4  22P_0201_25V8  [C_0201]  21.81 130.55 180 top
CA5  22P_0201_25V8  [C_0201]  22.38 131.09 270 top
CA6  22P_0201_25V8  [C_0201]  23.11 130.53 270 top
CA7  22P_0201_25V8  [C_0201]  23.85 131.09 270 top
CA8  0.1U_0201_10V6K  [C_0201]  20.32 129.85 270 top
CA9  2.2U_0402_6.3V6M  [C_0402]  21.06 129.73 270 top
CA10  0.1U_0201_10V6K  [C_0201]  4.83 119.92 90 top
CA11  1000P_0201_16V7K  [C_0201]  143.07 107.58 180 top
CA12  1000P_0201_16V7K  [C_0201]  144.82 101.67 180 top
CA13  0.1U_0201_10V6K  [C_0201]  32.25 85.75 90 top
CA14  0.1U_0201_10V6K  [C_0201]  34.04 85.65 90 top
CA15  10U_0402_6.3V6M  [C_0402]  33.3 85.44 90 top
CA16  2.2U_0402_6.3V6M  [C_0402]  39.52 85.44 90 top
CA17  680P_0201_25V7K  [C_0201]  43.29 85.61 180 top
CA18  0.1U_0201_10V6K  [C_0201]  31.9 84.11 270 top
CA19  680P_0201_25V7K  [C_0201]  43.81 83.72 270 top
CA20  10U_0402_6.3V6M  [C_0402]  29.82 83.3 180 top
CA21  10U_0402_6.3V6M  [C_0402]  29.82 82.43 180 top
CA22  0.1U_0201_10V6K  [C_0201]  31.19 82.36 180 top
CA23  10U_0603_10V6M  [C_0603]  42.33 82.24 0 top
CA24  0.1U_0201_10V6K  [C_0201]  40.92 82.06 0 top
CA25  0.1U_0201_10V6K  [C_0201]  40.92 81.5 0 top
CA26  0.1U_0201_10V6K  [C_0201]  31.22 81.24 180 top
CA27  10U_0603_10V6M  [C_0603]  42.33 80.97 0 top
CA28  1U_0201_6.3V6K  [C_0201]  31.22 80.66 180 top
CA29  0.1U_0201_10V6K  [C_0201]  40.7 80.08 0 top
CA30  680P_0201_25V7K  [C_0201]  43.76 79.5 270 top
CA31  680P_0201_25V7K  [C_0201]  43.76 78.03 270 top
CA32  2.2U_0402_6.3V6M  [C_0402]  36.66 76.19 0 top
CA33  0.1U_0201_10V6K  [C_0201]  16.33 144.72 0 bottom
CA34  100P_0201_25V8J  [C_0201]  10.97 142.7 270 bottom
CA35  0.1U_0402_10V7K  [C_0402]  16.36 141.19 90 bottom
CA36  10U_0603_6.3V6M  [C_0603]  10.25 138.75 180 bottom
CA37  10U_0603_6.3V6M  [C_0603]  10.25 137.56 180 bottom
CA38  10U_0603_6.3V6M  [C_0603]  11.4 136.43 90 bottom
CA39  0.1U_0201_10V6K  [C_0201]  14.05 136.36 270 bottom
CA40  2.2U_0402_6.3V6M  [C_0402]  10.03 135.6 90 bottom
CA41  10U_0603_6.3V6M  [C_0603]  8.99 135.09 90 bottom
CA42  0.1U_0201_10V6K  [C_0201]  11.09 135.68 0 bottom
CA43  0.1U_0201_10V6K  [C_0201]  12.84 135.17 0 bottom
CA44  0.1U_0201_10V6K  [C_0201]  16.79 135.12 180 bottom
CA45  0.1U_0201_10V6K  [C_0201]  15.04 135.12 0 bottom
CA46  0.1U_0201_10V6K  [C_0201]  9.88 134.91 0 bottom
CA47  22P_0201_25V8  [C_0201]  21.74 128.98 270 bottom
CA48  22P_0201_25V8  [C_0201]  20.14 129.82 270 bottom
CA49  22P_0201_25V8  [C_0201]  19.58 129.8 270 bottom
CA50  22P_0201_25V8  [C_0201]  21.18 128.96 270 bottom
CA51  1U_0402_6.3V6K  [C_0402]  6.07 128.11 90 bottom
CA52  1U_0402_6.3V6K  [C_0402]  6.12 127.24 270 bottom
CA53  2.2U_0402_6.3V6M  [C_0402]  6.12 125.47 270 bottom
CA54  2.2U_0402_6.3V6M  [C_0402]  8.81 124.48 90 bottom
CA55  2.2U_0402_6.3V6M  [C_0402]  9.88 124.45 90 bottom
CA56  0.1U_0201_10V6K  [C_0201]  13.86 124.75 0 bottom
CA57  0.1U_0201_10V6K  [C_0201]  15.04 124.74 270 bottom
CA58  0.1U_0201_10V6K  [C_0201]  12.88 124.69 270 bottom
CA59  0.1U_0201_10V6K  [C_0201]  11.96 124.67 270 bottom
CA60  0.1U_0201_10V6K  [C_0201]  11.12 124.64 270 bottom
CA61  4.7U_0402_6.3V6M  [C_0402]  15.77 124.04 0 bottom
CA62  2.2U_0402_6.3V6M  [C_0402]  14 124.04 270 bottom
CA63  10U_0603_6.3V6M  [C_0603]  10.26 123.43 180 bottom
CA64  2.2U_0402_6.3V6M  [C_0402]  6.15 123.71 270 bottom
CA65  4.7U_0402_6.3V6M  [C_0402]  12.42 123.05 270 bottom
CA66  10U_0603_6.3V6M  [C_0603]  11.35 122.99 270 bottom
CA67  0.1U_0201_10V6K  [C_0201]  13.73 121.99 180 bottom
CA68  100P_0201_25V7K  [C_0201]  14.33 121.97 270 bottom
CA69  1000P_0201_16V7K  [C_0201]  20.54 84.57 180 bottom
CA70  1000P_0201_16V7K  [C_0201]  18.76 84.57 0 bottom
CC1  0.1U_0201_10V6K  [C_0201]  56.16 126.33 180 top
CC2  1U_0201_6.3V6K  [C_0201]  56.35 125.55 180 top
CC3  0.1U_0201_10V6K  [C_0201]  69.18 124.65 0 top
CC4  22U_0603_6.3V6M  [C_0603]  68.77 123.76 0 top
CC5  0.1U_0201_10V6K  [C_0201]  53.57 123.17 90 top
CC6  0.1U_0201_10V6K  [C_0201]  72.03 122.3 90 top
CC7  0.1U_0201_10V6K  [C_0201]  68.58 122.28 90 top
CC8  0.1U_0201_10V6K  [C_0201]  69.14 122.28 90 top
CC9  0.1U_0201_10V6K  [C_0201]  69.75 122.28 90 top
CC10  0.1U_0201_10V6K  [C_0201]  70.89 122.28 90 top
CC11  0.1U_0201_10V6K  [C_0201]  71.48 122.28 90 top
CC12  0.1U_0201_10V6K  [C_0201]  70.33 122.27 90 top
CC13  0.1U_0201_10V6K  [C_0201]  57.26 122.04 90 top
CC14  0.1U_0201_10V6K  [C_0201]  73.25 121.14 90 top
CC15  0.1U_0201_10V6K  [C_0201]  73.81 121.14 90 top
CC16  0.1U_0201_10V6K  [C_0201]  74.4 121.14 90 top
CC17  0.1U_0201_10V6K  [C_0201]  74.98 121.14 90 top
CC18  0.1U_0201_10V6K  [C_0201]  75.56 121.14 90 top
CC19  0.1U_0201_10V6K  [C_0201]  76.12 121.14 90 top
CC20  0.1U_0201_10V6K  [C_0201]  71.5 121.11 90 top
CC21  0.1U_0201_10V6K  [C_0201]  72.08 121.11 90 top
CC22  0.1U_0201_10V6K  [C_0201]  72.67 121.11 90 top
CC23  0.1U_0201_10V6K  [C_0201]  68.58 121.08 90 top
CC24  0.1U_0201_10V6K  [C_0201]  69.16 121.08 90 top
CC25  0.1U_0201_10V6K  [C_0201]  69.75 121.08 90 top
CC26  0.1U_0201_10V6K  [C_0201]  70.33 121.08 90 top
CC27  0.1U_0201_10V6K  [C_0201]  70.92 121.08 90 top
CC28  0.1U_0201_10V6K  [C_0201]  56.68 120.86 90 top
CC29  0.1U_0201_10V6K  [C_0201]  68.59 120.49 0 top
CC30  0.1U_0201_10V6K  [C_0201]  72.77 120.53 270 top
CC31  0.1U_0201_10V6K  [C_0201]  73.33 120.53 270 top
CC32  0.1U_0201_10V6K  [C_0201]  73.89 120.53 270 top
CC33  0.1U_0201_10V6K  [C_0201]  74.45 120.53 270 top
CC34  0.1U_0201_10V6K  [C_0201]  75.01 120.53 270 top
CC35  0.1U_0201_10V6K  [C_0201]  75.59 120.53 270 top
CC36  0.1U_0201_10V6K  [C_0201]  76.15 120.53 270 top
CC37  1U_0402_6.3V6K  [C_0402]  55.92 120.08 180 top
CC38  0.1U_0201_10V6K  [C_0201]  68.59 119.93 0 top
CC39  0.1U_0201_10V6K  [C_0201]  56.7 120.2 270 top
CC40  0.1U_0201_10V6K  [C_0201]  57.26 120.2 270 top
CC41  0.1U_0201_10V6K  [C_0201]  71.65 119.33 90 top
CC42  0.1U_0201_10V6K  [C_0201]  72.21 119.33 90 top
CC43  0.1U_0201_10V6K  [C_0201]  68.59 119.34 0 top
CC44  0.1U_0201_10V6K  [C_0201]  71.08 119.32 180 top
CC45  0.1U_0201_10V6K  [C_0201]  68.59 118.79 0 top
CC46  0.1U_0201_10V6K  [C_0201]  71.08 118.76 180 top
CC47  0.1U_0201_10V6K  [C_0201]  71.67 118.76 0 top
CC48  0.1U_0201_10V6K  [C_0201]  62.73 118.66 180 top
CC49  0.1U_0201_10V6K  [C_0201]  56.71 118.58 0 top
CC50  0.1U_0201_10V6K  [C_0201]  68.59 118.2 0 top
CC51  0.1U_0201_10V6K  [C_0201]  71.08 118.2 180 top
CC52  0.1U_0201_10V6K  [C_0201]  71.67 118.2 0 top
CC53  0.1U_0201_10V6K  [C_0201]  62.74 118.07 180 top
CC54  0.1U_0201_10V6K  [C_0201]  56.71 117.92 0 top
CC55  0.1U_0201_10V6K  [C_0201]  71.08 117.64 180 top
CC56  0.1U_0201_10V6K  [C_0201]  71.67 117.64 0 top
CC57  0.1U_0201_10V6K  [C_0201]  68.59 117.62 0 top
CC58  0.1U_0201_10V6K  [C_0201]  62.74 117.49 180 top
CC59  0.1U_0201_10V6K  [C_0201]  71.67 117.08 0 top
CC60  0.1U_0201_10V6K  [C_0201]  68.59 117.06 0 top
CC61  1U_0201_6.3V6K  [C_0201]  55.94 117.01 180 top
CC62  0.1U_0201_10V6K  [C_0201]  56.63 117.01 0 top
CC63  0.1U_0201_10V6K  [C_0201]  71.07 117.07 270 top
CC64  0.1U_0201_10V6K  [C_0201]  54.74 117.03 270 top
CC65  0.1U_0201_10V6K  [C_0201]  71.67 116.53 0 top
CC66  0.1U_0201_10V6K  [C_0201]  55.94 116.37 180 top
CC67  0.1U_0201_10V6K  [C_0201]  71.69 115.97 0 top
CC68  0.1U_0201_10V6K  [C_0201]  71.01 115.84 180 top
CC69  0.1U_0201_10V6K  [C_0201]  71.69 115.41 0 top
CC70  0.1U_0201_10V6K  [C_0201]  71.03 115.28 180 top
CC71  0.1U_0201_10V6K  [C_0201]  71.69 114.85 0 top
CC72  0.1U_0201_10V6K  [C_0201]  71.03 114.72 180 top
CC73  0.1U_0201_10V6K  [C_0201]  71.69 114.29 0 top
CC74  0.1U_0201_10V6K  [C_0201]  71.03 114.14 180 top
CC75  22U_0603_6.3V6M  [C_0603]  55.88 113.99 180 top
CC76  0.1U_0201_10V6K  [C_0201]  62.73 113.91 180 top
CC77  0.1U_0201_10V6K  [C_0201]  71.69 113.71 0 top
CC78  0.1U_0201_10V6K  [C_0201]  71.03 113.58 180 top
CC79  22U_0603_6.3V6M  [C_0603]  56.97 114.09 270 top
CC80  0.1U_0201_10V6K  [C_0201]  62.73 113.35 180 top
CC81  0.1U_0201_10V6K  [C_0201]  71.69 113.15 0 top
CC82  0.1U_0201_10V6K  [C_0201]  71.01 113.02 180 top
CC83  0.1U_0201_10V6K  [C_0201]  62.73 112.79 180 top
CC84  22U_0603_6.3V6M  [C_0603]  53.09 111.34 90 top
CC85  0.1U_0201_10V6K  [C_0201]  57.3 109.9 270 top
CC86  0.1U_0201_10V6K  [C_0201]  57.3 108.63 270 top
CC87  0.1U_0201_10V6K  [C_0201]  57.3 106.58 90 top
CC88  22U_0603_6.3V6M  [C_0603]  55.54 104.43 0 top
CC89  22U_0603_6.3V6M  [C_0603]  55.54 103.22 0 top
CC90  0.1U_0201_10V6K  [C_0201]  89.99 100.92 90 top
CC91  0.1U_0201_10V6K  [C_0201]  66.62 143.01 180 bottom
CC92  22U_0603_6.3V6M  [C_0603]  77.81 128.55 90 bottom
CC93  1U_0402_6.3V6K  [C_0402]  79.08 128.66 90 bottom
CC94  0.1U_0201_10V6K  [C_0201]  68.45 126.82 90 bottom
CC95  0.1U_0201_10V6K  [C_0201]  70.31 126.8 90 bottom
CC96  0.1U_0201_10V6K  [C_0201]  66.89 126.79 90 bottom
CC97  0.1U_0201_10V6K  [C_0201]  76.1 126.75 90 bottom
CC98  0.1U_0201_10V6K  [C_0201]  75.46 126.75 90 bottom
CC99  0.1U_0201_10V6K  [C_0201]  72.44 126.75 90 bottom
CC100  0.1U_0201_10V6K  [C_0201]  54.01 122.93 180 bottom
CC101  0.1U_0201_10V6K  [C_0201]  56.92 121.54 90 bottom
CC102  0.1U_0201_10V6K  [C_0201]  56.29 121.54 90 bottom
CC103  0.1U_0201_10V6K  [C_0201]  57.56 121.49 90 bottom
CC104  0.1U_0201_10V6K  [C_0201]  81.43 119.38 90 bottom
CC105  0.1U_0201_10V6K  [C_0201]  58.55 119.36 270 bottom
CC106  1U_0201_6.3V6K  [C_0201]  57.96 119.36 270 bottom
CC107  0.1U_0201_10V6K  [C_0201]  81.43 118.37 270 bottom
CC108  1U_0402_6.3V6K  [C_0402]  58.39 118.02 180 bottom
CC109  0.1U_0201_10V6K  [C_0201]  58.48 117.26 180 bottom
CC110  0.1U_0201_10V6K  [C_0201]  58.45 116.08 90 bottom
CC111  0.1U_0201_10V6K  [C_0201]  58.58 115.48 180 bottom
CC112  0.1U_0201_10V6K  [C_0201]  58.58 114.87 180 bottom
CC113  0.1U_0201_10V6K  [C_0201]  58.58 114.26 180 bottom
CC114  22U_0603_6.3V6M  [C_0603]  57.02 114.02 270 bottom
CC115  1U_0201_6.3V6K  [C_0201]  58.55 113.11 270 bottom
CC116  0.1U_0201_10V6K  [C_0201]  67.67 107.38 180 bottom
CC117  0.1U_0201_10V6K  [C_0201]  65.61 107.27 270 bottom
CC118  0.1U_0201_10V6K  [C_0201]  67.08 106.2 90 bottom
CC119  0.1U_0201_10V6K  [C_0201]  65.01 104.69 0 bottom
CC120  0.1U_0201_10V6K  [C_0201]  89.45 102.92 180 bottom
CC121  22U_0603_6.3V6M  [C_0603]  66.87 102.63 0 bottom
CC122  0.1U_0201_10V6K  [C_0201]  89.45 102.33 180 bottom
CC123  0.1U_0201_10V6K  [C_0201]  87.69 101.39 180 bottom
CC124  0.1U_0201_10V6K  [C_0201]  55.98 113.06 270 top
CH1  0.1U_0201_10V6K  [C_0201]  54.61 131.1 180 top
CH2  0.1U_0201_10V6K  [C_0201]  54.64 130.52 180 top
CH3  0.1U_0201_10V6K  [C_0201]  52.84 130.5 0 top
CH4  0.1U_0201_10V6K  [C_0201]  53.43 129.94 180 top
CH5  1U_0402_6.3V6K  [C_0402]  57.21 128.44 180 top
CH6  0.1U_0201_10V6K  [C_0201]  57.28 123.79 270 top
CH7  0.1U_0201_10V6K  [C_0201]  45.49 122.09 90 top
CH8  0.1U_0201_10V6K  [C_0201]  48.08 114.04 90 top
CH9  15P_0402_50V8J  [C_0402]  58.01 129.68 180 bottom
CH10  15P_0402_50V8J  [C_0402]  58.01 128.79 180 bottom
CH11  1U_0402_6.3V6K  [C_0402]  54.69 127.32 0 bottom
CH12  0.1U_0201_10V6K  [C_0201]  56.32 126.74 0 bottom
CH13  0.1U_0201_10V6K  [C_0201]  51.9 115.84 0 bottom
CH14  15P_0402_50V8J  [C_0402]  56.49 109.69 90 bottom
CH15  15P_0402_50V8J  [C_0402]  56.49 108.83 0 bottom
CH16  0.1U_0201_10V6K  [C_0201]  69.15 107.3 0 bottom
CH17  0.1U_0201_10V6K  [C_0201]  69.15 106.75 0 bottom
CH18  0.1U_0201_10V6K  [C_0201]  64.26 105.29 90 bottom
CH19  0.1U_0201_10V6K  [C_0201]  63.7 105.29 90 bottom
CH20  0.22U_0201_6.3V6M  [C_0201]  66.83 104.78 90 bottom
CH21  0.22U_0201_6.3V6M  [C_0201]  66.27 104.78 90 bottom
CH22  0.22U_0201_6.3V6M  [C_0201]  66.23 104.1 0 bottom
CH23  0.22U_0201_6.3V6M  [C_0201]  66.23 103.55 0 bottom
CH24  1U_0402_6.3V6K  [C_0402]  24.92 18 270 bottom
CLIP1  EMI_Spring  [EMIST_SV-11A1M_1P]  17.6 152.71 90 bottom
CLIP2  EMI_Spring  [EMIST_SUL-12A2M_1P]  57.68 150.03 90 bottom
CLIP3  EMI_Spring  [EMIST_SUL-12A2M_1P]  200.11 149 90 bottom
CLIP4  EMI_Spring  [EMIST_SUL-12A2M_1P]  205.38 123.61 180 bottom
CLIP5  EMI_Spring  [EMIST_SV-11A1M_1P]  19.74 116.88 64.8 bottom
CLRP1  SHORT PADS  [SHORTPADS]  45.75 129.96 270 top
CLRP2  10K_0201_5%  [R_0201]  53.43 125.47 0 top
CT1  0.1U_0402_25V7K  [C_0402]  21.28 26.91 90 bottom
CT2  10U_0603_25V6M  [C_0603]  20.01 24.69 90 bottom
CT3  10U_0603_25V6M  [C_0603]  21.26 24.64 90 bottom
CT4  0.1U_0402_25V7K  [C_0402]  18.97 24.78 90 bottom
CT5  10U_0603_25V6M  [C_0603]  19.35 23.75 270 bottom
CU1  0.1U_0201_10V6K  [C_0201]  35.76 63.45 270 top
CU2  0.01U_0201_10V7K  [C_0201]  41.63 58.3 270 top
CV1  0.1U_0201_10V6K  [C_0201]  123.66 115.29 270 top
CV2  0.1U_0201_10V6K  [C_0201]  124.25 115.29 270 top
CV3  0.1U_0201_10V6K  [C_0201]  124.91 115.29 270 top
CV4  0.1U_0201_10V6K  [C_0201]  125.47 115.29 270 top
CV5  0.1U_0201_10V6K  [C_0201]  126.12 115.28 270 top
CV6  0.1U_0201_10V6K  [C_0201]  126.68 115.28 270 top
CV7  0.1U_0201_10V6K  [C_0201]  127.29 115.27 270 top
CV8  0.1U_0201_10V6K  [C_0201]  127.88 115.27 270 top
CV9  2.2U_0402_6.3V6M  [C_0402]  130.96 112.08 90 top
CV10  2.2U_0402_6.3V6M  [C_0402]  119.85 112.03 180 top
CV11  0.01U_0201_10V7K  [C_0201]  130.06 110.15 0 top
CV12  0_0201_5%  [R0201_0OHM]  130.8 109.57 180 top
CV13  0_0201_5%  [R0201_0OHM]  130.8 109.01 180 top
CV14  0.1U_0201_10V6K  [C_0201]  120.37 105.56 270 top
CV15  0.1U_0201_10V6K  [C_0201]  124.33 104.88 270 top
CV16  0.1U_0201_10V6K  [C_0201]  124.89 104.88 270 top
CV17  0.1U_0201_10V6K  [C_0201]  127.51 104.85 270 top
CV18  0.1U_0201_10V6K  [C_0201]  128.07 104.85 270 top
CV19  0.1U_0201_10V6K  [C_0201]  122.75 104.14 270 top
CV20  0.1U_0201_10V6K  [C_0201]  123.3 104.14 270 top
CV21  0.1U_0201_10V6K  [C_0201]  125.97 104.13 270 top
CV22  0.1U_0201_10V6K  [C_0201]  126.53 104.13 270 top
CV23  0.01U_0201_10V7K  [C_0201]  22.62 52 180 top
CV24  2.2U_0402_6.3V6M  [C_0402]  22.61 54.32 90 top
CV25  0.1U_0201_10V6K  [C_0201]  25.45 57.52 270 top
CV26  0.1U_0201_10V6K  [C_0201]  24.89 57.52 270 top
CV27  0.1U_0201_10V6K  [C_0201]  26.85 57.55 270 top
CV28  0.1U_0201_10V6K  [C_0201]  26.29 57.55 270 top
CV29  0.1U_0201_10V6K  [C_0201]  28.35 57.52 270 top
CV30  0.1U_0201_10V6K  [C_0201]  27.79 57.52 270 top
CV31  0.1U_0201_10V6K  [C_0201]  29.84 57.55 270 top
CV32  0.1U_0201_10V6K  [C_0201]  29.29 57.55 270 top
CV33  2.2U_0402_6.3V6M  [C_0402]  32.61 53.57 0 top
CV34  0.1U_0201_10V6K  [C_0201]  33.41 51.03 180 top
CV35  0.1U_0201_10V6K  [C_0201]  32.83 52.33 0 top
CV36  0.1U_0201_10V6K  [C_0201]  33.42 51.59 180 top
CV37  0.1U_0201_10V6K  [C_0201]  24.46 43.35 270 top
CV38  0.1U_0201_10V6K  [C_0201]  25.02 43.35 270 top
CV39  0.1U_0201_10V6K  [C_0201]  25.58 43.35 270 top
CV40  0.1U_0201_10V6K  [C_0201]  26.14 43.35 270 top
CV41  0.1U_0201_10V6K  [C_0201]  27 43.35 270 top
CV42  0.1U_0201_10V6K  [C_0201]  27.56 43.35 270 top
CV43  0.1U_0201_10V6K  [C_0201]  22.71 43.32 270 top
CV44  0.1U_0201_10V6K  [C_0201]  23.29 43.32 270 top
CV45  1U_0201_6.3V6K  [C_0201]  34.12 52.85 270 top
CX1  0.01U_0201_10V6K  [C_0201]  26.72 78.87 90 top
CX2  0.1U_0201_10V6K  [C_0201]  27.3 78.87 90 top
CX3  0.01U_0201_10V6K  [C_0201]  29.29 78.77 90 top
CX4  0.01U_0201_10V6K  [C_0201]  29.9 78.77 90 top
CX5  0.1U_0201_10V6K  [C_0201]  33.21 76.01 180 top
CX6  0.1U_0201_10V6K  [C_0201]  33.21 75.45 180 top
CX7  0.1U_0201_10V6K  [C_0201]  33.21 74.89 180 top
CX8  0.1U_0201_10V6K  [C_0201]  33.21 74.34 180 top
CX9  0.1U_0201_10V6K  [C_0201]  33.21 73.75 180 top
CX10  0.1U_0201_10V6K  [C_0201]  33.21 73.19 180 top
CX11  0.1U_0201_10V6K  [C_0201]  33.21 72.61 180 top
CX12  0.1U_0201_10V6K  [C_0201]  33.21 72.05 180 top
CX13  0.1U_0201_10V6K  [C_0201]  25.98 71.05 270 top
CX14  0.1U_0201_10V6K  [C_0201]  28.65 71.05 270 top
CX15  0.1U_0201_10V6K  [C_0201]  29.46 71 270 top
CX16  0.1U_0201_10V6K  [C_0201]  30.1 71 270 top
CX17  0.1U_0201_10V6K  [C_0201]  15.57 53.85 270 bottom
CX18  10U_0603_6.3V6M  [C_0603]  17.36 54.27 270 bottom
CX19  3.3P_0402_50V8C  [C_0402]  16.36 52.01 180 bottom
CX20  3.3P_0402_50V8C  [C_0402]  16.36 51.15 180 bottom
CX21  3.3P_0402_50V8C  [C_0402]  16.27 50.13 180 bottom
CX22  3.3P_0402_50V8C  [C_0402]  16.27 49.27 180 bottom
CX23  3.3P_0402_50V8C  [C_0402]  16.29 48.4 180 bottom
CX24  3.3P_0402_50V8C  [C_0402]  16.29 47.54 180 bottom
CX25  3.3P_0402_50V8C  [C_0402]  16.29 46.65 180 bottom
CX26  3.3P_0402_50V8C  [C_0402]  16.29 45.79 180 bottom
CZ1  0.1U_0402_25V6  [C_0402]  202.88 101.4 90 top
CZ2  0.1U_0402_25V6  [C_0402]  193.83 100.75 90 top
CZ3  0.1U_0402_25V6  [C_0402]  197.89 100.75 0 top
CZ4  0.1U_0402_25V6  [C_0402]  195.61 100.5 0 top
CZ5  0.1U_0402_25V6  [C_0402]  193.83 98.95 270 top
D1  -  [SDMK0340L-7-F_SOD323-2]  200.14 139.25 90 top
D2  -  [ESD207-B1-02EL_TSLP-2-19-2]  6.71 138.5 90 top
D3  -  [RB751S40T1G_SOD523-2]  197.65 135.27 180 top
D4  -  [BAT54CW-7-F_SOT323-3]  51.3 134.32 0 top
D5  -  [PJSOT24CW_SOT323-3]  42.66 126.41 270 top
D6  -  [BAT54CW-7-F_SOT323-3]  202.51 124.74 180 top
D7  -  [PJSOT24CW_SOT323-3]  50.86 123.88 180 top
D8  -  [ESD207-B1-02EL_TSLP-2-19-2]  6.91 123.54 0 top
D9  -  [BAT54HT1G_SOD323-2]  172.73 118.07 270 top
D10  -  [BAT54HT1G_SOD323-2]  174.37 118.07 270 top
D11  AZ5B25-01F_DFN0603P2Y  [ESD108-B1-CSP0201_WLL-2-1-2]  130.87 107.8 90 top
D12  -  [BAT54CW-7-F_SOT323-3]  116.81 108.28 0 top
D13  AZ5B25-01F_DFN0603P2Y  [ESD108-B1-CSP0201_WLL-2-1-2]  130.87 107.14 270 top
D14  AZ5B25-01F_DFN0603P2Y  [ESD108-B1-CSP0201_WLL-2-1-2]  124.29 103.62 180 top
D15  AZ5B25-01F_DFN0603P2Y  [ESD108-B1-CSP0201_WLL-2-1-2]  124.97 103.62 0 top
D16  -  [BAT54CW-7-F_SOT323-3]  101.83 103.6 270 top
D17  AZ5B25-01F_DFN0603P2Y  [ESD108-B1-CSP0201_WLL-2-1-2]  127.53 103.58 180 top
D18  AZ5B25-01F_DFN0603P2Y  [ESD108-B1-CSP0201_WLL-2-1-2]  128.21 103.58 0 top
D19  AZ5B25-01F_DFN0603P2Y  [ESD108-B1-CSP0201_WLL-2-1-2]  122.71 102.86 180 top
D20  AZ5B25-01F_DFN0603P2Y  [ESD108-B1-CSP0201_WLL-2-1-2]  123.38 102.86 0 top
D21  AZ5B25-01F_DFN0603P2Y  [ESD108-B1-CSP0201_WLL-2-1-2]  125.87 102.8 180 top
D22  AZ5B25-01F_DFN0603P2Y  [ESD108-B1-CSP0201_WLL-2-1-2]  126.54 102.8 0 top
D23  AZ5B25-01F_DFN0603P2Y  [ESD108-B1-CSP0201_WLL-2-1-2]  23.65 35.28 270 top
D24  AZ5B25-01F_DFN0603P2Y  [ESD108-B1-CSP0201_WLL-2-1-2]  24.51 35.28 270 top
D25  AZ5B25-01F_DFN0603P2Y  [ESD108-B1-CSP0201_WLL-2-1-2]  25.48 35.26 270 top
D26  AZ5B25-01F_DFN0603P2Y  [ESD108-B1-CSP0201_WLL-2-1-2]  26.34 35.26 270 top
D27  AZ5B25-01F_DFN0603P2Y  [ESD108-B1-CSP0201_WLL-2-1-2]  27.33 35.26 270 top
D28  AZ5B25-01F_DFN0603P2Y  [ESD108-B1-CSP0201_WLL-2-1-2]  28.19 35.26 270 top
D29  AZ5B25-01F_DFN0603P2Y  [ESD108-B1-CSP0201_WLL-2-1-2]  29.18 35.26 270 top
D30  AZ5B25-01F_DFN0603P2Y  [ESD108-B1-CSP0201_WLL-2-1-2]  29.97 35.26 270 top
D31  AZ5B25-01F_DFN0603P2Y  [ESD108-B1-CSP0201_WLL-2-1-2]  21.82 29.77 270 top
D32  AZ5B25-01F_DFN0603P2Y  [ESD108-B1-CSP0201_WLL-2-1-2]  22.53 29.77 270 top
D33  AZ5B25-01F_DFN0603P2Y  [ESD108-B1-CSP0201_WLL-2-1-2]  23.24 29.77 270 top
D34  AZ5B25-01F_DFN0603P2Y  [ESD108-B1-CSP0201_WLL-2-1-2]  24.08 29.77 270 top
D35  -  [PJSOT24CW_SOT323-3]  196.59 137.4 270 bottom
D37  -  [BAT54CW-7-F_SOT323-3]  112.07 106.19 90 bottom
D38  ESD218-B1-02ELS TSSLP-2-4  [ESD101-B1-02ELS_TSSLP-2-4-2]  15.32 24.9 90 bottom
D39  AZ5B25-01F_DFN0603P2Y  [ESD108-B1-CSP0201_WLL-2-1-2]  17.42 22.18 90 bottom
D40  AZ5B25-01F_DFN0603P2Y  [ESD108-B1-CSP0201_WLL-2-1-2]  16.71 22.18 90 bottom
